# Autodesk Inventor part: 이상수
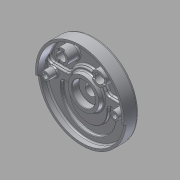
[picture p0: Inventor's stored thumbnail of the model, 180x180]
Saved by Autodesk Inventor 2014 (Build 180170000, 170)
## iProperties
Created: 2015-05
Part Number: 이상수
Material: 알루미늄 6061
Document SubType Name: Modeling
Designer: USER
Density: 2.71 g/cm^3
Appearance: 알루미늄 - 평지
Mass: 1091.66 g
Surface Area: 1039.9 cm^2
Volume: 402.825 cm^3
Author: USER
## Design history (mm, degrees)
sketch "스케치1"
  geometry: C1 r 95 at (0, 0); 1 further point
  constraints: 1 centre point, 1 coincident
  dimensions: "d0" = 190 diameter of C1
extrude "돌출1" new body sketch "스케치1" distance "d1" = 32; taper "d2" = 0 deg
sketch "스케치2"
  geometry: L1 (0, 0)-(-94.638, -8.28); L2 (0, 0)-(94.638, -8.28); L3 (-90, 0)-(90, 0); A1 r 95 centre (0, 0) between (94.638, -8.28) and (-94.638, -8.28) reference
  constraints: 6 end point, 2 point on circle, 1 coincident, 1 horizontal, 1 midpoint
  dimensions: "d4" = 5 deg angle of L2 L3; "d5" = 5 deg angle of L1 L3
extrude "돌출2" cut sketch "스케치2" distance "d6" = 5; taper "d7" = 0 deg
sketch "스케치3"
  geometry: C1 r 95 at (0, 0) reference; C2 r 25 at (0, 0)
  constraints: 1 centre point, 1 coincident
  dimensions: "d8" = 50 diameter of C2
extrude "돌출3" join sketch "스케치3" distance "d9" = 12; taper "d10" = -15 deg
sketch "스케치4"
  geometry: L1 (-89.196, 12)-(-40.249, 12); L2 (40.249, 12)-(89.196, 12); A1 r 95 centre (0, 0) between (94.638, -8.28) and (-94.638, -8.28) reference; A2 r 42 centre (0, 0) between (40.249, 12) and (-40.249, 12); A3 r 90 centre (0, 0) between (89.196, 12) and (-89.196, 12); 1 further point
  constraints: 4 end point, 4 point on circle, 2 centre point, 2 coincident, 2 horizontal
  dimensions: "d11" = 84 diameter of A2; "d12" = 180 diameter of A3; "d14" = 12 distance from line of point (0, 0) L2; "d15" = 12 distance from line of point (0, 0) L1
extrude "돌출4" cut sketch "스케치4" distance "d16" = 25; taper "d17" = 0 deg
fillet "모깎기1" dims "d18" = 10
sketch "스케치5"
  geometry: L1 (-47.117, 12)-(-76.916, 12) reference; L2 (76.916, 12)-(47.117, 12) reference; C1 r 42 at (0, 0); C2 r 90 at (0, 0); A1 r 42 centre (0, 0) between (38.056, 17.769) and (-38.056, 17.769) reference; A2 r 10 centre (-47.117, 22) between (-47.117, 12) and (-38.056, 17.769) reference; A3 r 10 centre (-76.916, 22) between (-86.53, 24.75) and (-76.916, 12) reference; A4 r 90 centre (0, 0) between (86.53, 24.75) and (-86.53, 24.75) reference; A5 r 10 centre (76.916, 22) between (76.916, 12) and (86.53, 24.75) reference; A6 r 10 centre (47.117, 22) between (38.056, 17.769) and (47.117, 12) reference; A7 r 95 centre (0, 0) between (94.638, -8.28) and (-94.638, -8.28) reference
  constraints: 2 centre point, 2 coincident
  dimensions: "d19" = 84 diameter of C1; "d20" = 180 diameter of C2
extrude "돌출5" cut sketch "스케치5" distance "d21" = 18; taper "d22" = 0 deg
sketch "스케치7"
  geometry: C1 r 15 at (-40, 52); C2 r 15 at (40, 52); A1 r 90 centre (0, 0) between (86.53, 24.75) and (-86.53, 24.75) reference
  constraints: 2 centre point, 1 equal radius, 1 horizontal alignment
  dimensions: "d23" = 30 diameter of C1; "d24" = 40 horizontal distance of C1.centre A1.centre; "d25" = 80 distance of C2.centre C1.centre; "d26" = 52 vertical distance of A1.centre C1.centre
extrude "돌출6" join sketch "스케치7" distance "d27" = 25; taper "d28" = 0 deg
sketch "스케치8"
  geometry: C1 r 15 at (-40, -52) reference; C2 r 15 at (40, -52) reference; C3 r 10 at (40, -52); C4 r 10 at (-40, -52)
  constraints: 2 centre point, 2 coincident
  dimensions: "d29" = 20 diameter of C3; "d30" = 20 diameter of C4
extrude "돌출7" cut sketch "스케치8" stored distance "d31" = 0; taper "d32" = 0 deg
sketch "스케치9"
  geometry: L1 (-6, 13.748)-(-6, -13.748); L2 (6, 13.748)-(6, -13.748); L3 (66.252, 6)-(93.748, 6); L4 (66.252, -6)-(93.748, -6); C1 r 10 at (0, 0) reference; C2 r 10 at (80, 0) reference; A1 r 15 centre (0, 0) between (-6, 13.748) and (6, 13.748) reference; A2 r 15 centre (80, 0) between (93.748, 6) and (93.748, -6) reference; 1 further point
  constraints: 8 end point, 8 point on circle, 2 parallel, 1 perpendicular, 1 vertical
  dimensions: "d33" = 6 distance from line of C1.centre L1; "d34" = 12 distance between parallel lines of L2 L1; "d35" = 6 distance from line of L3 C2.centre; "d36" = 12 distance between parallel lines of L4 L3
extrude "돌출8" cut sketch "스케치9" distance "d37" = 3; taper "d38" = 0 deg
sketch "스케치10"
  geometry: C1 r 25 at (0, 0) reference; C2 r 9 at (74, 0); C3 r 9 at (-74, 0)
  constraints: 2 centre point, 2 horizontal alignment, 1 equal radius
  dimensions: "d39" = 18 diameter of C2; "d40" = 148 distance of C3.centre C2.centre; "d41" = 74 distance of C3.centre C1.centre
extrude "돌출9" join sketch "스케치10" distance "d42" = 32; taper "d43" = 0 deg
sketch "스케치11"
  geometry: C1 r 9 at (74, 0) reference; C2 r 9 at (-74, 0) reference; 2 further points
  constraints: 2 coincident
hole "구멍1" sketch "스케치11" at (74, 0), (-74, 0) diameter "d44" = 11; stored, may be unused: countersink angle "d48" = 90 deg, drill point angle "d50" = 118 deg; dims "d45" = 6, "d46" = 18, "d47" = 11, "d49" = 8
sketch "스케치12"
  geometry: C1 r 42 at (0, 0); A1 r 90 centre (0, 0) between (-86.53, 24.75) and (86.53, 24.75) reference
  constraints: 1 centre point, 1 coincident
  dimensions: "d51" = 84 diameter of C1
extrude "돌출10" cut sketch "스케치12" stored distance "d52" = 0; taper "d53" = 0 deg
sketch "스케치13"
  geometry: C1 r 35 at (0, 0); A1 r 90 centre (0, 0) between (-86.53, 24.75) and (86.53, 24.75) reference
  constraints: 1 centre point, 1 coincident
  dimensions: "d54" = 70 diameter of C1
extrude "돌출11" join sketch "스케치13" distance "d55" = 10; taper "d56" = -10 deg
sketch "스케치14"
  geometry: C1 r 33.237 at (0, 0) reference; 1 further point
  constraints: 1 coincident
hole "구멍2" sketch "스케치14" at (0, 0) diameter "d57" = 23; stored, may be unused: countersink angle "d61" = 90 deg, drill point angle "d63" = 118 deg; dims "d58" = 6, "d59" = 50, "d60" = 15, "d62" = 8
sketch "스케치15"
  geometry: L1 (-76.916, 12)-(-47.117, 12) reference; L2 (-50, -19)-(-50, -14); L3 (50, -19)-(50, -14); L4 (-59, -19)-(-59, -14); L5 (-41, -19)-(-41, -14); L6 (41, -19)-(41, -14); L7 (59, -19)-(59, -14); A1 r 35 centre (0, 0) between (-25.426, 24.053) and (25.426, 24.053) reference; A2 r 41 centre (0, -19) between (-41, -19) and (41, -19); A3 r 59 centre (0, -19) between (-59, -19) and (59, -19); A4 r 50 centre (0, -19) between (-50, -19) and (50, -19); A5 r 50 centre (0, -19) between (25.426, 24.053) and (-25.426, 24.053); A6 r 9 centre (50, -14) between (59, -14) and (41, -14); A7 r 9 centre (-50, -14) between (-41, -14) and (-59, -14); 3 further points
  constraints: 14 point on circle, 12 end point, 6 centre point, 6 tangent, 5 coincident, 3 parallel, 1 horizontal, 1 vertical, 1 vertical alignment, 10 other
  dimensions: "d65" = 19 dimension on A1.centre; "d68" = 41 radius of A2; "d69" = 59 radius of A3; "d72" = 50 radius of A4; "d73" = 5 distance of L2.start L2.end; "d74" = 5 distance of L3.start L3.end; "d75" = 18 diameter of A6; "d76" = 18 diameter of A7
extrude "돌출12" cut sketch "스케치15" distance "d77" = 7; taper "d78" = 0 deg
fillet "모깎기2" dims "d79" = 3
fillet "모깎기3" dims "d80" = 3
fillet "모깎기4" dims "d81" = 1
fillet "모깎기5" dims "d82" = 0.3
fillet "모깎기6" dims "d83" = 3
fillet "모깎기7" dims "d84" = 5
fillet "모깎기8" dims "d85" = 3
fillet "모깎기11" dims "d98" = 3
chamfer "모따기1" distance "d99" = 1; stored, may be unused: second distance "d100" = 2, angle "d101" = 45 deg
chamfer "모따기2" distance "d102" = 1; stored, may be unused: second distance "d103" = 2, angle "d104" = 45 deg
sketch "스케치19"
  geometry: L1 (0, 0)-(36.062, 36.062); L2 (36.062, 36.062)-(50.912, 50.912); L3 (0, 0)-(-36.062, 36.062); L4 (-36.062, 36.062)-(-50.912, 50.912); L5 (0, 0)-(0, 82.919); C1 r 90 at (0, 0) reference; A1 r 51 centre (0, 0) between (36.062, 36.062) and (-36.062, 36.062); A2 r 72 centre (0, 0) between (50.912, 50.912) and (-50.912, 50.912); 1 further point
  constraints: 10 end point, 4 point on circle, 2 centre point, 2 coincident, 1 midpoint, 1 point on line, 1 vertical, 1 other
  dimensions: "d119" = 90 deg angle of L3 L1; "d120" = 51 radius of A1; "d121" = 72 radius of A2
extrude "돌출14" join sketch "스케치19" distance "d110" = 5; taper "d111" = 0 deg
fillet "모깎기15" dims "d122" = 3
fillet "모깎기19" dims "d130" = 5
fillet "모깎기20" dims "d131" = 3
sketch "스케치22"
  geometry: C1 r 68 at (0, 0); A1 r 56 centre (0, 0) between (35.904, 42.975) and (-35.904, 42.975) reference
  constraints: 1 centre point, 1 coincident, 1 other
  dimensions: "d132" = 136 diameter of C1
feature "엠보싱4" sketch "스케치22" dims "d133" = 0.5, "d134" = 0
node "솔리드1"
node "투영된 루프1"
other parameters: "d13" = 12, "d66" = 82, "d67" = 118, "d86" = 144
